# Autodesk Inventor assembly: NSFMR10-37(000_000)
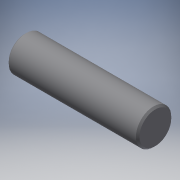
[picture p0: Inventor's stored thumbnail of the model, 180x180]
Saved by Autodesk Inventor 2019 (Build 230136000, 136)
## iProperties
Category: PARTsolutions
Company: MISUMI
Created: 2022-11
Part Number: NSFMR10-37(000_000)
Catalog Web Link: www.cadenas.de
Description: NSFMR, SFMR, PSFMR, SSFMR, SSSFMR, NSFHR, SFHR, PSFHR, PPSFHR SSFHR, SSSFHR, NSFR, SFR, PSFR, PPSFR, SSFR, SSSFR, HFR, PHFR_shaft-Rotary Shafts - Straight -
Vendor: MISUMI
Document SubType Name: Assembly
Designer: psAdmin
Manufacturer: MISUMI
Mass: 2.89838 g
Surface Area: 13.0042 cm^2
Volume: 2.89838 cm^3
Density: 1 g/cm^3
Title: NSFMR10-37
Author: Cadenas PARTsolutions
Comments: Rotary Shafts - Straight -
PSOL_IDENT_0: {$CADENAS_DATA/23d-libs/misumi/metric/11_rotary_shafts/psfr_asmtab.prj},572 {VTYP=3D},{STYP=ASSTAB},
PSOL_IDENT_1: {NB=NSFMR10-37(000_000)},{LINA=NSFMR10-37},{NN=NSFMR, SFMR, PSFMR, SSFMR, SSSFMR, NSFHR, SFHR, PSFHR
PSOL_IDENT_2: , PPSFHR SSFHR, SSSFHR, NSFR, SFR, PSFR, PPSFR, SSFR, SSSFR, HFR, PHFR_shaft},{DATE=28.04.2022 02:06
PSOL_IDENT_3: :52},{GEOMDATE=27.07.2021 08:19:30},{VERSION=},{LINEID=30},{WBVAR=TS,MAT,ST,ALT1,L,ALT2,KC,A,WKC,C,K
PSOL_IDENT_4: ,E,KZ,Z,ALT3,FC,GALT3,WFC,J,WALT3,V,ALT4,SFC,SG,AG,ALT10,KWC,ALT11,WC,ALT6,TA,TB,ALT5,UC,ALT7,SC,ALT
PSOL_IDENT_5: 32,CD,ALT34,TCJ,WTCJ,XT,HCJ,WHCJ,XH},{WBNUMERIC=L,KC,A,WKC,C,K,E,KZ,Z,FC,GALT3,WFC,J,WALT3,V,SFC,SG,
PSOL_IDENT_6: AG,KWC,WC,TA,TB,UC,SC,TCJ,WTCJ,XT,HCJ,WHCJ,XH}  {NB=NSFMR10-37(000_000)},{LINA=NSFMR10-37},{KT=DUMMY
PSOL_IDENT_7: },{PN=NSFMR10-37},{TYPE=NSFMR},{TS=M},{TSALG= 'M','h9 (Cold-drawn)','H','h7 (Ground)','','g6 (Ground
PSOL_IDENT_8: )' },{MAT=S45C},{MATALG= 'S45C','S45C Equivalent', 'SUS304','304 Stainless Steel' },{ST=},{STALG= ''
PSOL_IDENT_9: ,'-','BO','Black Oxide', 'ENP','Electroless Nickel Plating' },{D=10.0},{ALT1=},{L=37.0},{LALG=[15:80
PSOL_IDENT_10: 0/0.1]},{LMIN=15},{LMAX=800},{NOTE=Not Applicable},{ALT2=},{ALT2ALG= '', 'w/o Key Grooves','KC','wit
PSOL_IDENT_11: h KC (Key Groove)','WKC','with WKC (Two Key Grooves)','KCWKC','with KC + WKC (Three Key Grooves)','K
PSOL_IDENT_12: Z','with KC + WKC + KZ (Four Key Grooves)' },{ALT2PN=},{KC=0.0},{KCALG=[0]},{KCMIN=0},{KCMAX=0},{A=0
PSOL_IDENT_13: .0},{AALG=[0]},{AMIN=3},{AMAX=0},{WKC=0.0},{WKCALG=[0]},{WKCMIN=0},{WKCMAX=0},{C=0.0},{CALG=[0]},{CM
PSOL_IDENT_14: IN=3},{CMAX=0},{K=0.0},{KALG=[0]},{KMIN=0},{KMAX=32},{E=0.0},{EALG=[0]},{EMIN=3},{EMAX=35},{KZ=0.0},
PSOL_IDENT_15: {KZALG=[0]},{KZMIN=39},{KZMAX=34},{Z=0.0},{ZALG=[0]},{ZMIN=3},{ZMAX=37},{CIFKC=1},{CIFWKC=1},{CIFK=1
PSOL_IDENT_16: },{CIFKZ=2},{PCUT3D=0.000},{QCUT3D=0},{BB=3},{BBALT2=3},{TT=1.8},{TTALT2=1.8},{ALT3=},{ALT3ALG= '', '
PSOL_IDENT_17: w/o Set Screw Flat','FC','with FC (Adds a Set Screw Flat)','WFC','with WFC (Adds Two Set Screw Flats
PSOL_IDENT_18: )','FCWFC','with FC + WFC (Adds Three Set Screw Flats)' },{ALT3PN=},{FC=0},{FCALG=[0]},{FCMIN=0},{FC
PSOL_IDENT_19: MAX=36},{GALT3=0},{GALT3ALG=[0]},{GALT3MIN=1},{GALT3MAX=37},{GALT3MAX2=31},{GALT3MAX3=34},{WFC=0},{W
PSOL_IDENT_20: FCALG=[0]},{WFCMIN=0},{WFCMIN2=2},{WFCMAX=33},{WFCMAX2=-3},{WFCMAX3=-4},{J=0},{JALG=[0]},{JMIN=1},{J
PSOL_IDENT_21: MAX=34},{JMAX2=-2},{JMAX3=-5},{WALT3=0},{WALT3ALG=[0]},{WALT3MIN=0},{WALT3MIN2=39},{WALT3MAX=34},{WA
PSOL_IDENT_22: LT3MAX2=34},{WALT3MAX3=34},{V=0},{VALG=[0]},{VMIN=1},{VMAX=35},{VMAX2=35},{VMAX3=35},{CIFFC=0},{ALT4=
PSOL_IDENT_23: },{ALT4ALG= '', 'w/o SFC (2 Set Screw Flats (Angle Specified))', 'SFC'  , 'with SFC (2 Set Screw Fla
PSOL_IDENT_24: ts (Angle Specified))'},{ALT4PN=},{SFC=0},{SFCALG=[0]},{SFCMIN=0},{SFCMAX=36},{SG=0},{SGALG=[0]},{SG
PSOL_IDENT_25: MIN=1},{SGMAX=37},{AG=0},{AGALG=[0]},{H=0.0},{CIFSFC=0},{ALT10=},{ALT10ALG= '', 'w/o KWC (2 Set Scre
PSOL_IDENT_26: w Flats at both ends)', 'KWC', 'with KWC (2 Set Screw Flats at both ends)' },{ALT10PN=},{KWC=0},{KWC
PSOL_IDENT_27: ALG=[0]},{KWCMIN=1},{KWCMAX=17.5},{WALT10=8},{ALT11=},{ALT11ALG= '','Not applicable' },{ALT11PN=},{W
PSOL_IDENT_28: C=0.0},{WCALG=[0]},{ALT6=},{ALT6ALG= '','w/o Retaining Ring Groove','TA','with TA (Retaining Ring Gr
PSOL_IDENT_29: oove)','TB','with TB (Retaining Ring Groove)','TATB','with TA + TB (Two Retaining Ring Grooves)' },{
PSOL_IDENT_30: ALT6PN=},{TA=0.0},{TAALG=[0]},{TAMIN=2},{TAMAX=0},{TB=0.0},{TBALG=[0]},{TBMIN=2},{TBMAX=0},{DDALT6=0
PSOL_IDENT_31: .0},{MM=0.00},{ALT5=},{ALT5ALG= '', 'w/o UC (Slit Cam Groove)', 'UC', 'with UC (Slit Cam Groove)'},{
PSOL_IDENT_32: ALT5PN=},{UC=0},{UCALG=[0]},{UCMIN=1},{UCMAX=31},{DDALT5=0},{LL1=0},{ALT7=},{ALT7ALG= '', 'w/o SC (W
PSOL_IDENT_33: rench Flats)', 'SC', 'with SC (Wrench Flats)'},{ALT7PN=},{SC=0},{SCALG=[0]},{SCMIN=0},{SCMAX=29},{WA
PSOL_IDENT_34: LT7=0},{LL2=0},{LL2ALG=8},{CIFSC=0},{ALT32=},{ALT32ALG=  '','w/o CD (Changes Part D Chamfering)','-C
PSOL_IDENT_35: D', 'with CD (Changes Part D Chamfering)' },{ALT32PN=},{CD=},{CDALG= '','N/A' },{CD3D=0.5},{CIF32=0}
PSOL_IDENT_36: ,{CIF320=0},{CIFTA=0},{CIFTB=0},{ERRORPN=},{ERRORALT23=OK},{ERRORALT24=OK},{ERRORALT25=OK},{ERRORALT
PSOL_IDENT_37: 26=OK},{ERRORALT27=OK},{ERRORALT210=OK},{ERRORALT34=OK},{ERRORALT35=OK},{ERRORALT36=OK},{ERRORALT37=
PSOL_IDENT_38: OK},{ERRORALT310=OK},{ERRORALT45=OK},{ERRORALT46=OK},{ERRORALT47=OK},{ERRORALT410=OK},{ERRORALT56=OK
PSOL_IDENT_39: },{ERRORALT57=OK},{ERRORALT510=OK},{ERRORALT610=OK},{ERRORALT75=OK},{ERRORALT76=OK},{ERRORALT710=OK}
PSOL_IDENT_40: ,{ALT34=},{ALT34ALG= '','Not applicable'},{TCJ=0},{WTCJ=0},{XT=0},{TM=4},{TCJALG=[0]},{TCJMIN=0.000}
PSOL_IDENT_41: ,{TCJMAX=15.000},{TCJMAX1=15.000},{HCJ=0},{WHCJ=0},{XH=0},{HP=4},{HCJALG=[0]},{HCJMIN=0.000},{HCJMAX=
PSOL_IDENT_42: 15.000},{HCJMAX1=15.000},{LCJ=0},{LMINX=15},{XCJMIN=4.000},{XALG=[0]},{XCJMAX=15.000},{PPATH=11_comp
PSOL_IDENT_43: onents/psfr/psfr_asmtpl.prj},{WHCJMIN=0.000},{WTCJMIN=0.000},{WTCJALG=[0]},{WHCJALG=[0]},{XHCJMIN=4.
PSOL_IDENT_44: 000},{XHALG=[0]}
NB: NSFMR10-37(000_000)
NN: NSFMR, SFMR, PSFMR, SSFMR, SSSFMR, NSFHR, SFHR, PSFHR, PPSFHR SSFHR, SSSFHR, NSFR, SFR, PSFR, PPSFR, SSFR, SSSFR, HFR, PHFR_shaft
NT: Rotary Shafts - Straight -
NBSYN: $PN.($ALT34.$TCJ.$WTCJ.$XT._$HCJ.$WHCJ.$XH.)
LINA: NSFMR10-37
CATALOG: Misumi
PN: NSFMR10-37
TS: h9 (Cold-drawn)
MAT: S45C Equivalent
ST: -
D: 10
ALT1: w/o LKC (Changes L Tolerance)
L: 37
ALT2: w/o Key Grooves
KC: 0
A: 0
WKC: 0
C: 0
K: 0
E: 0
KZ: 0
Z: 0
ALT3: w/o Set Screw Flat
FC: 0
GALT3: 0
WFC: 0
J: 0
WALT3: 0
V: 0
ALT4: w/o SFC (2 Set Screw Flats (Angle Specified))
SFC: 0
SG: 0
AG: 0
H: 0
ALT10: w/o KWC (2 Set Screw Flats at both ends)
KWC: 0
ALT11: Not applicable
WC: 0
ALT6: w/o Retaining Ring Groove
TA: 0
TB: 0
DDALT6: 0
MM: 0
ALT5: w/o UC (Slit Cam Groove)
UC: 0
DDALT5: 0
LL1: 0
ALT7: w/o SC (Wrench Flats)
SC: 0
WALT7: 0
LL2: 0
ALT32: w/o CD (Changes Part D Chamfering)
CD: N/A
ALT34: Not applicable
TCJ: 0
WTCJ: 0
XT: 0
HCJ: 0
WHCJ: 0
XH: 0
SUPPLIER: MISUMI
ARTICLENO: NSFMR10-37(000_000)
BOMINFO: NSFMR10-37
CREATOR: CADENAS GmbH
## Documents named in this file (2)
- e:\temp\worker_COMMON_6\temp\tmp_2540_164_9sSFn\format_0\NSFMR10-37(000_000).iam
- e:\temp\worker_COMMON_6\temp\tmp_2540_164_9sSFn\format_0\NSFMR10-37(000_000)_s.ipt
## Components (1 placed, 1 different names)
1. NSFMR10-37(000_000)_s:1
